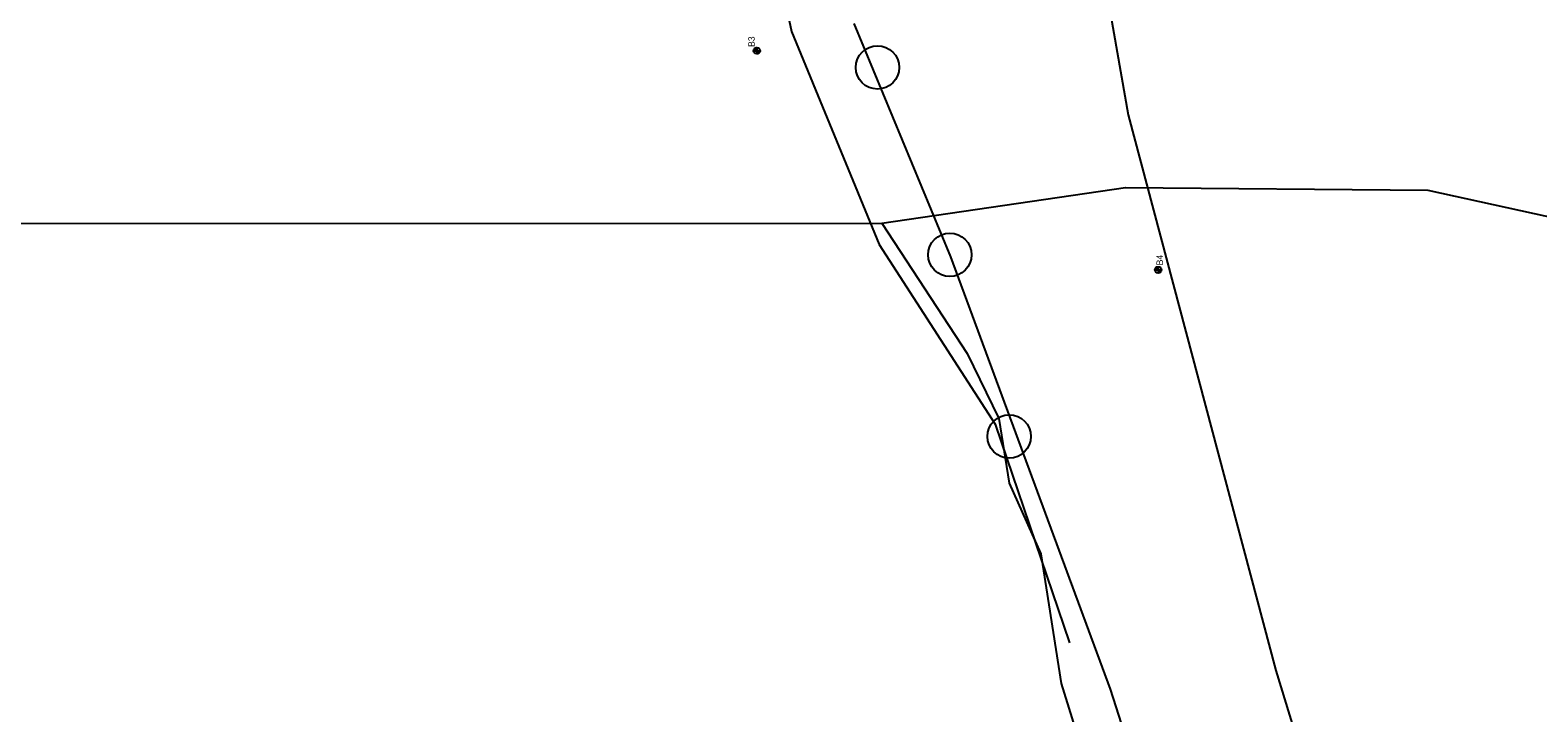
# Model space of a CAD drawing. Extents: x 331323 to 388339, y 121519 to 205315.
# Drawn here: x 360253 to 362580, y 128453 to 129507 of the extents above; entities that cross this region are included whole.
import ezdxf

# ---------------------------------------------------------------- set-up
doc = ezdxf.new("R2010")
doc.units = 0
for name, color, linetype in [('CE-TOPO-CONC-SLAB', 7, 'Continuous'), ('E_SOIL_BORE1 [KAPUR_CADDS_LEVELS]', 7, 'Continuous'), ('Level 2', 7, 'Continuous'), ('Level 57', 7, 'Continuous'), ('P_MARK', 7, 'Continuous')]:
    doc.layers.add(name, color=color, linetype=linetype)

msp = doc.modelspace()

# ---------------------------------------------------------------- linework, layer by layer
at = {"layer": 'CE-TOPO-CONC-SLAB'}
for centre in [(361561, 129449.2), (361672.7, 129159.9), (361764.4, 128879.4)]:
    msp.add_circle(centre, 33.5, dxfattribs=at)
at = {"layer": 'Level 2'}
for points in [[(361373.1, 130238.2), (361362.5, 129949.9), (361389.4, 129688.1), (361428.3, 129504.5), (361563.5, 129175.9)], [(361798.4, 130229.7), (361947.9, 129375.8), (362175.7, 128517.9), (362415.7, 127734.4), (362566.7, 127294.1)], [(361524.8, 129516.9), (361674, 129156.9), (361920.1, 128489.2), (362093.1, 127949.7), (362303.7, 127294.9)], [(361563.5, 129175.9), (361742.6, 128898.2), (361857.6, 128560.7)]]:
    msp.add_lwpolyline(points, dxfattribs=at)
at = {"layer": 'Level 57'}
for points in [[(356898.1, 130184.5), (357114.6, 130149.2), (357147.7, 130115.6), (357162.2, 129882.1), (357236.6, 129814.8), (357470.3, 129829.4), (357720.5, 129827.1), (358061.4, 129715.7), (358317.1, 129413.3), (358466.5, 129328.7), (358907.9, 129266.3), (359023.9, 129181.9), (359257.5, 129196.5), (359783.1, 129208.4), (361567.8, 129208.9)], [(361567.8, 129208.9), (361943.6, 129263.8), (362410.6, 129259.6), (363242.9, 129077.1), (364142.3, 128935.6), (364799.9, 128796.3), (365107.8, 128726.9)], [(361567.8, 129208.9), (361699.4, 129007.7), (361748.5, 128907.3), (361764.3, 128807.1), (361813.3, 128698.3), (361844.8, 128498), (361966.3, 128105.3), (361981.6, 127955.1), (362014.2, 127871.5), (362029.3, 127704.7), (362094.1, 127495.8), (362191.5, 127211.5)]]:
    msp.add_lwpolyline(points, dxfattribs=at)
at = {"layer": 'P_MARK'}
for p, q in [((361374.9, 129480), (361374.9, 129470)), ((361369.9, 129475), (361379.9, 129475)), ((361989.2, 129136.5), (361999.2, 129136.5)), ((361994.2, 129141.5), (361994.2, 129131.5))]:
    msp.add_line(p, q, dxfattribs=at)
for centre in [(361374.9, 129475), (361994.2, 129136.5)]:
    msp.add_circle(centre, 5, dxfattribs=at)
for centre, radius, start, end in [((361374.9, 129475), 4.5, 89.9869, 179.9869), ((361374.9, 129475), 4, 89.9869, 179.9869), ((361374.9, 129475), 3.5, 89.9869, 179.9869), ((361374.9, 129475), 3, 89.9869, 179.9869), ((361374.9, 129475), 2.5, 89.9869, 179.9869), ((361374.9, 129475), 2, 89.9869, 179.9869), ((361374.9, 129475), 1.5, 89.9869, 179.9869), ((361374.9, 129475), 1, 89.9869, 179.9869), ((361374.9, 129475), 0.5, 89.9869, 179.9869), ((361374.9, 129475), 4.5, 269.9869, 359.9869), ((361374.9, 129475), 4, 269.9869, 359.9869), ((361374.9, 129475), 3.5, 269.9869, 359.9869), ((361374.9, 129475), 3, 269.9869, 359.9869), ((361374.9, 129475), 2.5, 269.9869, 359.9869), ((361374.9, 129475), 2, 269.9869, 359.9869), ((361374.9, 129475), 1.5, 269.9869, 359.9869), ((361374.9, 129475), 1, 269.9869, 359.9869), ((361374.9, 129475), 0.5, 269.9869, 359.9869), ((361994.2, 129136.5), 4.5, 89.9869, 179.9869), ((361994.2, 129136.5), 4, 89.9869, 179.9869), ((361994.2, 129136.5), 3.5, 89.9869, 179.9869), ((361994.2, 129136.5), 3, 89.9869, 179.9869), ((361994.2, 129136.5), 2.5, 89.9869, 179.9869), ((361994.2, 129136.5), 2, 89.9869, 179.9869), ((361994.2, 129136.5), 1.5, 89.9869, 179.9869), ((361994.2, 129136.5), 1, 89.9869, 179.9869), ((361994.2, 129136.5), 0.5, 89.9869, 179.9869), ((361994.2, 129136.5), 4.5, 269.9869, 359.9869), ((361994.2, 129136.5), 4, 269.9869, 359.9869), ((361994.2, 129136.5), 3.5, 269.9869, 359.9869), ((361994.2, 129136.5), 3, 269.9869, 359.9869), ((361994.2, 129136.5), 2.5, 269.9869, 359.9869), ((361994.2, 129136.5), 2, 269.9869, 359.9869), ((361994.2, 129136.5), 1.5, 269.9869, 359.9869), ((361994.2, 129136.5), 1, 269.9869, 359.9869), ((361994.2, 129136.5), 0.5, 269.9869, 359.9869)]:
    msp.add_arc(centre, radius, start, end, dxfattribs=at)

# ---------------------------------------------------------------- texts
at = {"layer": 'E_SOIL_BORE1 [KAPUR_CADDS_LEVELS]'}
for s, p in [('B3', (361371.5, 129480.7)), ('B4', (362001.6, 129143.5))]:
    msp.add_text(s, height=10, rotation=89.9869, dxfattribs=at).set_placement(p)

doc.saveas('drawing.dxf')
